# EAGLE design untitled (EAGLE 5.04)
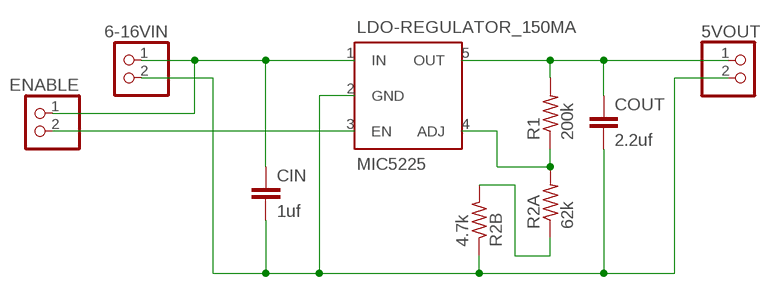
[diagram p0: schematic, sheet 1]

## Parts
5VOUT  PINHD-1X2  [1X02]
6-16VIN  PINHD-1X2  [1X02]
CIN  1uf  C-EUC1206  [C1206]
COUT  2.2uf  C-EU050-024X044  [C050-024X044]
ENABLE  PINHD-1X2  [1X02]
LDO-REGULATOR_150MA  MIC5225  [TSOT23-5]
R1  200k  R-US_R1206  [R1206]
R2A  62k  R-US_0204/7  [0204/7]
R2B  4.7k  R-US_R1206  [R1206]

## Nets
N$1: 6-16VIN.1 CIN.1 ENABLE.1 LDO-REGULATOR_150MA.1(IN)
N$2: 5VOUT.2 6-16VIN.2 CIN.2 COUT.2 LDO-REGULATOR_150MA.2(GND) R2B.1
N$3: 5VOUT.1 COUT.1 LDO-REGULATOR_150MA.5(OUT) R1.2
N$4: LDO-REGULATOR_150MA.4(ADJ) R1.1 R2A.2
N$5: ENABLE.2 LDO-REGULATOR_150MA.3(EN)
N$6: R2A.1 R2B.2

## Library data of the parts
5VOUT 6-16VIN ENABLE = pinhead:PINHD-1X2: PIN HEADER
CIN COUT = resistor:C-EU: CAPACITOR, European symbol
LDO-REGULATOR_150MA = trl:MIC5225
R1 R2A R2B = resistor:R-US_: RESISTOR, American symbol

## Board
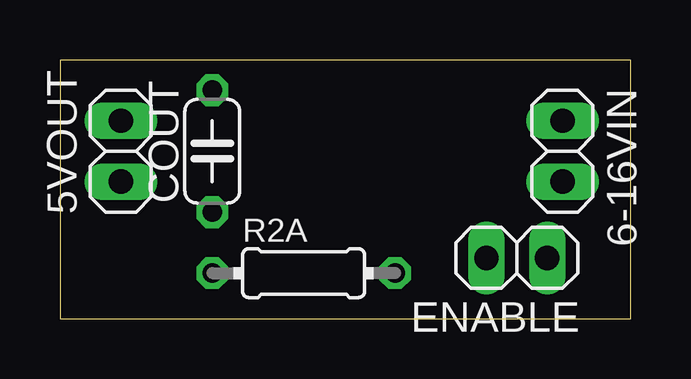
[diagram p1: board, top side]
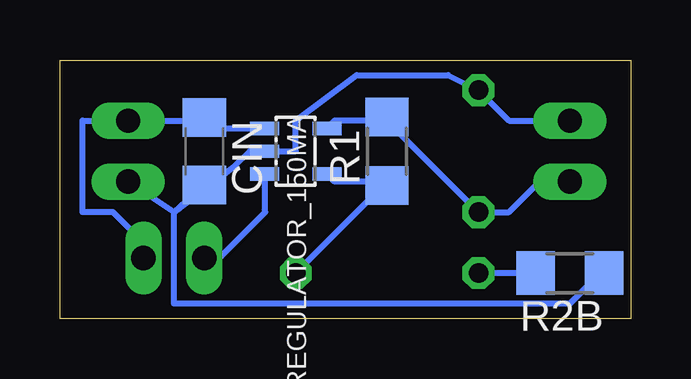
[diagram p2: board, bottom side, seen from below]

Size 23.8 x 10.79 mm. Coordinates in mm from the lower left corner, seen from the top.
Outline: 0,0 23.8,0 23.8,10.79 0,10.79 0,0
Copper layers (1*16): Top 0.035mm / dielectric 1.5mm / Bottom 0.035mm
Design rules "default": minimum track width 10mil, minimum drill 24mil, track to track 8mil, track to pad 8mil, pad to pad 8mil, via to via 8mil, smd to smd 8mil, copper to edge 40mil, drill to drill 8mil, minimum pad ring 10mil, minimum via ring 8mil, stop-mask expansion 4mil, vias tented up to drill 0mil, thermal gap 10mil

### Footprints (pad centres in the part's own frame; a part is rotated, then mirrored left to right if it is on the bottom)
1X02 = drill 1.016 long: 1 -1.27,0; 2 1.27,0
C1206 = smd 1.6 x 1.8: 1 -1.4,0; 2 1.4,0
C050-024X044 = drill 0.813 octagon: 1 -2.54,0; 2 2.54,0
TSOT23-5 = smd 0.55 x 1.2: 1 -0.95,-1.3; 2 0,-1.3; 3 0.95,-1.3; 4 0.95,1.3; 5 -0.95,1.3
R1206 = smd 1.6 x 1.803: 1 -1.422,0; 2 1.422,0
0204/7 = drill 0.813 octagon: 1 -3.81,0; 2 3.81,0

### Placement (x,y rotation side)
5VOUT  2.54,6.99 90 top
6-16VIN  20.95,6.99 270 top
CIN  17.78,6.99 270 bottom
COUT  6.35,6.99 90 top
ENABLE  19.05,2.54 180 top
LDO-REGULATOR_150MA  13.97,6.99 270 bottom
R1  10.16,6.99 90 bottom
R2A  10.16,1.91 0 top
R2B  2.54,1.91 180 bottom

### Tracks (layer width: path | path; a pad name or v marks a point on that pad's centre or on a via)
N$1
  Bottom 0.254: ENABLE.1 20.32,3.17 21.59,4.45 22.86,4.45 22.86,8.26 6-16VIN.1 17.78,8.26 CIN.1 17.33,7.93 LDO-REGULATOR_150MA.1
N$2
  Bottom 0.254: 5VOUT.2 5.08,8.26 COUT.2 7.62,10.16 11.43,10.16 13.97,8.26 13.97,6.99 LDO-REGULATOR_150MA.2 15.88,6.99 16.51,6.35 19.05,4.45 | 19.05,4.45 19.05,0.64 2.54,0.64 1.27,1.91 R2B.1 | 19.05,4.45 6-16VIN.2 | 19.05,4.45 CIN.2
N$3
  Bottom 0.254: 10.16,8.26 COUT.1 5.08,4.45 3.81,5.71 5VOUT.1 | 10.16,8.26 R1.2 | 10.16,8.26 12.35,8.26 LDO-REGULATOR_150MA.5
N$4
  Bottom 0.254: 10.16,5.71 R2A.2 | R1.1 10.16,5.71 | 10.16,5.71 12.35,5.71 LDO-REGULATOR_150MA.4
N$5
  Bottom 0.254: ENABLE.2 17.14,2.54 15.24,4.45 15.24,6 LDO-REGULATOR_150MA.3
N$6
  Bottom 0.254: R2A.1 R2B.2 3.81,1.91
